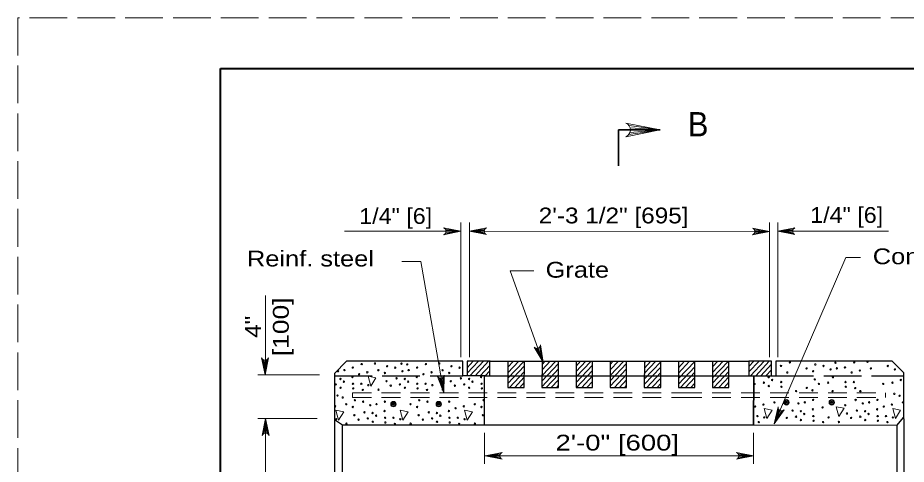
# Model space of a CAD drawing. Extents: x 1083.1 to 1117.1, y 697.4 to 719.4.
# Drawn here: x 1083.13 to 1091.89, y 714.95 to 719.35 of the extents above; entities that cross this region are included whole.
import ezdxf
from ezdxf.enums import TextEntityAlignment as Align

# ---------------------------------------------------------------- set-up
doc = ezdxf.new("R2010")
doc.units = 0
doc.header["$LTSCALE"] = 0.062
doc.linetypes.add('LONG_DASHED', pattern=[7.5, 6, -1.5])
doc.linetypes.add('MEDIUM_DASHED', pattern=[4.5, 3, -1.5])
doc.layers.add('1', color=7, linetype='Continuous', lineweight=13)

msp = doc.modelspace()

# ---------------------------------------------------------------- linework, layer by layer
at = {"layer": '1', "lineweight": 25}
for p, q in [((1085.12642, 718.85408), (1116.62642, 718.85408)), ((1090.6065, 715.96242), (1090.6065, 715.81983)), ((1087.783, 715.81983), (1087.783, 715.96233)), ((1087.78858, 715.96233), (1090.33942, 715.96233)), ((1090.56425, 715.96233), (1090.33942, 715.96233)), ((1090.34, 715.96233), (1090.34, 715.81983)), ((1090.56425, 715.81983), (1090.56425, 715.96233)), ((1090.56425, 715.81983), (1090.56425, 715.96233)), ((1087.73, 715.33367), (1087.73, 715.81983)), ((1087.73642, 715.81983), (1087.78242, 715.81983)), ((1087.78242, 715.81983), (1090.3455, 715.81983)), ((1086.24967, 715.39908), (1086.24967, 714.6575)), ((1086.25133, 715.38933), (1086.32992, 715.33367)), ((1091.80083, 715.33333), (1091.8655, 715.40867)), ((1091.86725, 715.39333), (1091.86725, 714.669)), ((1086.32992, 714.65083), (1086.32992, 715.33367)), ((1086.32992, 715.33367), (1087.73642, 715.33367)), ((1087.73642, 715.33367), (1090.38633, 715.33367)), ((1090.38633, 715.33367), (1091.80083, 715.33333)), ((1091.80083, 714.66842), (1091.80083, 715.33333))]:
    msp.add_line(p, q, dxfattribs=at)
at = {"layer": '1', "lineweight": 35}
for q in [(1089.46333, 718.24725), (1089.05217, 717.89125)]:
    msp.add_line((1089.05217, 718.24725), q, dxfattribs=at)
at = {"layer": '1'}
for p, q in [((1089.15517, 718.20008), (1089.46333, 718.24725)), ((1089.15875, 718.28983), (1089.46333, 718.24725)), ((1089.16683, 718.21983), (1089.46333, 718.24725)), ((1089.16908, 718.26875), (1089.46333, 718.24725)), ((1089.17225, 718.24725), (1089.46333, 718.24725)), ((1087.49642, 716.00258), (1087.49642, 717.33425)), ((1087.58358, 716.00375), (1087.58358, 717.33425)), ((1090.544, 716.00267), (1090.544, 717.33425)), ((1090.62583, 716.0035), (1090.62583, 717.33425)), ((1086.35, 717.24558), (1087.49642, 717.24558)), ((1087.34233, 717.22208), (1087.49642, 717.24558)), ((1087.34417, 717.26692), (1087.49642, 717.24558)), ((1087.34817, 717.23192), (1087.49642, 717.24558)), ((1087.34933, 717.25633), (1087.49642, 717.24558)), ((1087.35092, 717.24558), (1087.49642, 717.24558)), ((1087.73583, 717.26808), (1087.58358, 717.24675)), ((1087.73075, 717.2575), (1087.58358, 717.24675)), ((1087.72917, 717.24675), (1087.58358, 717.24675)), ((1087.73183, 717.23308), (1087.58358, 717.24675)), ((1087.73767, 717.22325), (1087.58358, 717.24675)), ((1087.58358, 717.24675), (1090.54392, 717.24458)), ((1090.38983, 717.221), (1090.54392, 717.24458)), ((1090.39167, 717.26583), (1090.54392, 717.24458)), ((1090.39567, 717.23083), (1090.54392, 717.24458)), ((1090.39683, 717.25533), (1090.54392, 717.24458)), ((1090.39842, 717.24458), (1090.54392, 717.24458)), ((1090.77817, 717.26783), (1090.62583, 717.2465)), ((1090.773, 717.25725), (1090.62583, 717.2465)), ((1090.77142, 717.2465), (1090.62583, 717.2465)), ((1090.77417, 717.23283), (1090.62583, 717.2465)), ((1090.78, 717.22292), (1090.62583, 717.2465)), ((1091.71783, 717.2465), (1090.62583, 717.2465)), ((1086.91533, 716.94842), (1087.10275, 716.94842)), ((1087.32858, 715.65258), (1087.10275, 716.94842)), ((1088.30708, 715.95333), (1087.98292, 716.85592)), ((1088.219, 716.85592), (1087.98292, 716.85592)), ((1085.57192, 715.8295), (1085.57192, 716.613)), ((1088.23817, 716.0915), (1088.30842, 715.95467)), ((1088.24983, 716.09008), (1088.30842, 715.95467)), ((1088.2605, 716.09217), (1088.30842, 715.95467)), ((1088.27258, 716.09917), (1088.30842, 715.95467)), ((1088.27992, 716.10792), (1088.30842, 715.95467)), ((1085.54433, 715.98183), (1085.56567, 715.8295)), ((1085.55483, 715.97667), (1085.56567, 715.8295)), ((1085.58917, 715.98358), (1085.56567, 715.8295)), ((1085.57933, 715.97775), (1085.56567, 715.8295)), ((1085.56567, 715.97508), (1085.56567, 715.8295)), ((1087.55875, 715.84417), (1087.67042, 715.96233)), ((1087.55875, 715.89792), (1087.61967, 715.96233)), ((1087.55875, 715.95158), (1087.56892, 715.96233)), ((1087.58658, 715.81992), (1087.72117, 715.96233)), ((1087.63742, 715.81992), (1087.77192, 715.96233)), ((1087.68817, 715.81992), (1087.783, 715.92042)), ((1087.96208, 715.74167), (1088.124, 715.91317)), ((1087.96217, 715.7955), (1088.11942, 715.96192)), ((1087.96233, 715.90317), (1088.01808, 715.96217)), ((1087.96233, 715.84933), (1088.06875, 715.96208)), ((1088.12417, 715.96192), (1087.96242, 715.96233)), ((1087.96242, 715.95692), (1087.9675, 715.96225)), ((1088.29842, 715.71517), (1088.4605, 715.88667)), ((1088.2985, 715.76908), (1088.4605, 715.9405)), ((1088.29867, 715.82292), (1088.43008, 715.962)), ((1088.29875, 715.93042), (1088.32883, 715.96225)), ((1088.29875, 715.87667), (1088.37942, 715.96208)), ((1088.46058, 715.96192), (1088.29892, 715.96233)), ((1088.635, 715.80758), (1088.78083, 715.96192)), ((1088.635, 715.75375), (1088.79692, 715.92525)), ((1088.63517, 715.86142), (1088.73025, 715.96208)), ((1088.63525, 715.91525), (1088.67958, 715.96225)), ((1088.79708, 715.96192), (1088.63533, 715.96233)), ((1088.97133, 715.71575), (1089.13333, 715.88725)), ((1088.97142, 715.76958), (1089.13342, 715.94108)), ((1088.97158, 715.82342), (1089.1025, 715.962)), ((1088.97167, 715.931), (1089.00117, 715.96225)), ((1088.97167, 715.87725), (1089.05175, 715.96208)), ((1089.1335, 715.96192), (1088.97175, 715.96233)), ((1089.30775, 715.733), (1089.46975, 715.9045)), ((1089.30783, 715.78683), (1089.46983, 715.95833)), ((1089.308, 715.84067), (1089.42267, 715.96208)), ((1089.30808, 715.8945), (1089.372, 715.96217)), ((1089.30817, 715.94833), (1089.32142, 715.96225)), ((1089.46992, 715.96192), (1089.30825, 715.96233)), ((1089.64425, 715.73758), (1089.80625, 715.909)), ((1089.64433, 715.79142), (1089.8055, 715.96192)), ((1089.64442, 715.84508), (1089.75483, 715.96208)), ((1089.6445, 715.899), (1089.70425, 715.96217)), ((1089.64458, 715.95275), (1089.65358, 715.96225)), ((1089.80642, 715.96192), (1089.64467, 715.96233)), ((1089.98075, 715.74517), (1090.14267, 715.91658)), ((1089.98083, 715.799), (1090.13475, 715.96192)), ((1089.981, 715.96033), (1089.98283, 715.96225)), ((1089.981, 715.90667), (1090.03342, 715.96217)), ((1089.981, 715.85283), (1090.08417, 715.96208)), ((1090.14283, 715.96192), (1089.98108, 715.96233)), ((1090.34, 715.85683), (1090.43975, 715.96233)), ((1090.34, 715.9105), (1090.38892, 715.96225)), ((1090.35592, 715.81983), (1090.4905, 715.96233)), ((1090.40658, 715.81983), (1090.54125, 715.96233)), ((1090.45733, 715.81983), (1090.56425, 715.93308)), ((1090.50808, 715.81983), (1090.56425, 715.87933)), ((1086.10392, 715.8295), (1085.49325, 715.8295)), ((1087.28275, 715.79933), (1087.32858, 715.65258)), ((1087.294, 715.796), (1087.32858, 715.65258)), ((1087.30483, 715.79617), (1087.32858, 715.65258)), ((1087.31792, 715.80108), (1087.32858, 715.65258)), ((1087.32667, 715.80842), (1087.32858, 715.65258)), ((1087.53633, 715.81983), (1087.73642, 715.81983)), ((1087.73883, 715.81983), (1087.783, 715.86667)), ((1087.97842, 715.70525), (1088.12392, 715.85925)), ((1088.02908, 715.70517), (1088.12383, 715.8055)), ((1088.33975, 715.70525), (1088.46033, 715.83283)), ((1088.63992, 715.70525), (1088.79683, 715.87142)), ((1088.69058, 715.70517), (1088.79667, 715.81758)), ((1089.01217, 715.70525), (1089.13317, 715.83342)), ((1089.33233, 715.70525), (1089.46975, 715.85067)), ((1089.383, 715.70508), (1089.46958, 715.79683)), ((1089.66458, 715.70525), (1089.80617, 715.85517)), ((1089.71517, 715.70508), (1089.806, 715.80133)), ((1089.99383, 715.70525), (1090.14258, 715.86275)), ((1090.04442, 715.70517), (1090.14242, 715.80892)), ((1090.38692, 715.81983), (1090.38692, 715.3415)), ((1088.07967, 715.705), (1088.12375, 715.75167)), ((1088.39042, 715.70508), (1088.46025, 715.779)), ((1088.441, 715.70492), (1088.46017, 715.72517)), ((1088.74117, 715.705), (1088.79667, 715.76375)), ((1088.79183, 715.70492), (1088.79658, 715.71)), ((1089.06275, 715.70508), (1089.13317, 715.77958)), ((1089.11342, 715.70492), (1089.13308, 715.72575)), ((1089.43358, 715.705), (1089.46958, 715.74308)), ((1089.76575, 715.705), (1089.806, 715.7475)), ((1090.09508, 715.705), (1090.14233, 715.75508)), ((1086.26542, 715.47833), (1086.29108, 715.38092)), ((1090.63208, 715.49233), (1090.59, 715.34442)), ((1090.63967, 715.48333), (1090.59, 715.34442)), ((1090.64883, 715.47758), (1090.59, 715.34442)), ((1090.67383, 715.47583), (1090.59, 715.34442)), ((1090.66242, 715.4745), (1090.59, 715.34442)), ((1090.63117, 715.4375), (1090.59, 715.34442)), ((1086.0795, 715.39908), (1085.49325, 715.39908)), ((1085.54833, 715.245), (1085.57192, 715.39908)), ((1085.55825, 715.25083), (1085.57192, 715.39908)), ((1085.57192, 711.969), (1085.57192, 715.39908)), ((1085.57192, 715.2535), (1085.57192, 715.39908)), ((1085.58267, 715.25192), (1085.57192, 715.39908)), ((1085.59325, 715.24675), (1085.57192, 715.39908)), ((1087.73, 715.25717), (1087.73, 714.9505)), ((1090.38633, 715.25717), (1090.38633, 714.9505)), ((1087.88875, 715.05017), (1087.73642, 715.02883)), ((1087.88358, 715.03958), (1087.73642, 715.02883)), ((1087.8335, 715.02883), (1087.73642, 715.02883)), ((1087.882, 715.02883), (1087.73642, 715.02883)), ((1087.88467, 715.01517), (1087.73642, 715.02883)), ((1087.8905, 715.00525), (1087.73642, 715.02883)), ((1087.73642, 715.02883), (1089.35158, 715.02883)), ((1089.35158, 715.02883), (1090.38633, 715.02883)), ((1090.23225, 715.00525), (1090.38633, 715.02883)), ((1090.234, 715.05017), (1090.38633, 715.02883)), ((1090.23808, 715.01517), (1090.38633, 715.02883)), ((1090.23917, 715.03958), (1090.38633, 715.02883)), ((1090.24075, 715.02883), (1090.38633, 715.02883)), ((1090.28925, 715.02883), (1090.38633, 715.02883))]:
    msp.add_line(p, q, dxfattribs=at)
at = {"layer": '1', "linetype": 'LONG_DASHED', "lineweight": 25}
msp.add_line((1086.24967, 715.81983), (1087.5165, 715.81983), dxfattribs=at)
at = {"layer": '1', "linetype": 'LONG_DASHED'}
for p, q in [((1086.42908, 715.65267), (1086.42908, 715.60392)), ((1091.68783, 715.65267), (1091.68783, 715.60392))]:
    msp.add_line(p, q, dxfattribs=at)
at = {"layer": '1', "linetype": 'MEDIUM_DASHED'}
for p, q in [((1086.42908, 715.65267), (1089.69008, 715.65267)), ((1089.69008, 715.65267), (1091.68783, 715.65267)), ((1086.42908, 715.60392), (1089.69008, 715.60392)), ((1089.69008, 715.60392), (1091.68783, 715.60392))]:
    msp.add_line(p, q, dxfattribs=at)
at = {"layer": '1', "linetype": 'LONG_DASHED'}
msp.add_lwpolyline([(1083.12642, 697.35408), (1117.12642, 697.35408), (1117.12642, 719.35408), (1083.12642, 719.35408)], close=True, dxfattribs=at)
at = {"layer": '1', "lineweight": 25}
for points in [[(1116.62642, 697.85408), (1085.12642, 697.85408), (1085.12642, 718.85408)], [(1091.86725, 715.39358), (1091.86725, 715.84767), (1091.75275, 715.96408), (1090.6065, 715.96242)], [(1087.73642, 715.81983), (1087.5165, 715.81983), (1087.5165, 715.96233), (1086.37, 715.96233), (1086.24967, 715.84292), (1086.24967, 715.39908)], [(1087.78858, 715.96233), (1087.55875, 715.96233), (1087.55875, 715.81983)], [(1087.96242, 715.96233), (1087.96192, 715.70525), (1088.12367, 715.70483), (1088.12417, 715.96192)], [(1088.29892, 715.96233), (1088.29833, 715.70525), (1088.46008, 715.70483), (1088.46058, 715.96192)], [(1088.63533, 715.96233), (1088.63483, 715.70525), (1088.7965, 715.70483), (1088.79708, 715.96192)], [(1088.97175, 715.96233), (1088.97125, 715.70525), (1089.133, 715.70483), (1089.1335, 715.96192)], [(1089.30825, 715.96233), (1089.30767, 715.70525), (1089.46942, 715.70483), (1089.46992, 715.96192)], [(1089.64467, 715.96233), (1089.64417, 715.70525), (1089.80583, 715.70483), (1089.80642, 715.96192)], [(1089.98108, 715.96233), (1089.98058, 715.70525), (1090.14233, 715.70483), (1090.14283, 715.96192)], [(1090.3455, 715.81983), (1090.38633, 715.81983), (1090.6065, 715.81983)], [(1090.38633, 715.33367), (1090.38692, 715.81983), (1090.38633, 715.33367)]]:
    msp.add_lwpolyline(points, dxfattribs=at)
at = {"layer": '1', "lineweight": 40}
msp.add_lwpolyline([(1085.12642, 718.85408), (1116.62642, 718.85408), (1116.62642, 697.85408), (1085.12642, 697.85408)], close=True, dxfattribs=at)
msp.add_lwpolyline([(1085.12642, 718.85408), (1116.62642, 718.85408), (1116.62642, 697.85408), (1085.12642, 697.85408)], close=True, dxfattribs=at)
at = {"layer": '1'}
for points in [[(1089.12692, 718.17992), (1089.46333, 718.24725), (1089.12692, 718.3145)], [(1087.32825, 717.212), (1087.49642, 717.24558), (1087.32825, 717.27925)], [(1087.75183, 717.21308), (1087.58358, 717.24675), (1087.75183, 717.28042)], [(1090.37575, 717.21092), (1090.54392, 717.24458), (1090.37575, 717.27817)], [(1090.79408, 717.21283), (1090.62583, 717.2465), (1090.79408, 717.28017)], [(1090.59, 715.34442), (1091.29525, 716.986), (1091.44108, 716.986)], [(1088.28483, 716.12458), (1088.30842, 715.95467), (1088.22125, 716.1025)], [(1085.59925, 715.99775), (1085.56567, 715.8295), (1085.532, 715.99775)], [(1087.33433, 715.824), (1087.32858, 715.65258), (1087.268, 715.813)], [(1086.29108, 715.38092), (1086.34333, 715.46308), (1086.26542, 715.47833)], [(1090.68875, 715.48467), (1090.59, 715.34442), (1090.62725, 715.51183)], [(1085.53825, 715.23083), (1085.57192, 715.39908), (1085.60558, 715.23083)], [(1087.90467, 714.99517), (1087.73642, 715.02883), (1087.90467, 715.0625)], [(1090.21808, 714.99517), (1090.38633, 715.02883), (1090.21808, 715.0625)]]:
    msp.add_lwpolyline(points, dxfattribs=at)
for points in [[(1086.58267, 715.81408), (1086.60833, 715.71683), (1086.6605, 715.799)], [(1086.89983, 715.47833), (1086.9255, 715.38092), (1086.97775, 715.46308)], [(1087.53425, 715.47833), (1087.55992, 715.38092), (1087.61208, 715.46308)], [(1090.49008, 715.4955), (1090.51575, 715.39817), (1090.568, 715.48033)], [(1091.20017, 715.51442), (1091.22583, 715.41708), (1091.278, 715.49925)], [(1091.75892, 715.4955), (1091.78458, 715.39817), (1091.83675, 715.48033)]]:
    msp.add_lwpolyline(points, close=True, dxfattribs=at)
at = {"layer": '1', "linetype": 'LONG_DASHED', "lineweight": 25}
msp.add_lwpolyline([(1090.6065, 715.81983), (1091.67575, 715.81983), (1091.86725, 715.81983)], dxfattribs=at)
at = {"layer": '1'}
for centre, radius in [((1086.8323, 715.53968), 0.02655), ((1086.8323, 715.53968), 0.01987), ((1086.8323, 715.53968), 0.01149), ((1086.8323, 715.53968), 0.00431), ((1087.27929, 715.53968), 0.02655), ((1087.27929, 715.53968), 0.02655), ((1087.27929, 715.53968), 0.01987), ((1087.27929, 715.53968), 0.01149), ((1087.27929, 715.53968), 0.00431), ((1090.70991, 715.55725), 0.02655), ((1090.70991, 715.55725), 0.01987), ((1090.70991, 715.55725), 0.01149), ((1090.70991, 715.55725), 0.00431), ((1091.15691, 715.55725), 0.02655), ((1091.15691, 715.55725), 0.02655), ((1091.15691, 715.55725), 0.01987), ((1091.15691, 715.55725), 0.01149), ((1091.15691, 715.55725), 0.00431)]:
    msp.add_circle(centre, radius, dxfattribs=at)
for centre, radius, start, end in [((1089.09975, 718.2473), 0.07261, 292.08605, 67.91218), ((1087.31464, 717.24565), 0.03631, 292.08605, 67.91218), ((1087.76538, 717.24681), 0.03631, 112.08782, 247.91395), ((1090.36215, 717.24459), 0.03631, 292.08605, 67.91218), ((1090.80768, 717.24653), 0.03631, 112.08782, 247.91395), ((1088.24856, 716.12636), 0.03631, 221.29191, 357.11803), ((1085.5656, 716.01131), 0.03631, 202.08782, 337.91395), ((1087.29891, 715.83191), 0.03631, 211.46424, 347.29037), ((1090.66345, 715.51071), 0.03631, 178.25218, 314.07831), ((1085.57195, 715.21728), 0.03631, 22.08782, 157.91395), ((1087.91824, 715.02886), 0.03631, 112.08782, 247.91395), ((1090.20453, 715.02886), 0.03631, 292.08605, 67.91218)]:
    msp.add_arc(centre, radius, start, end, dxfattribs=at)
for centre in [(1091.50946, 715.9579), (1086.34855, 715.87575), (1086.43166, 715.90015), (1086.51931, 715.93441), (1086.65037, 715.94073), (1086.68373, 715.87452), (1086.77027, 715.91353), (1086.85105, 715.89931), (1086.91105, 715.93922), (1086.96841, 715.93099), (1086.98295, 715.87575), (1087.06606, 715.90015), (1087.15371, 715.93441), (1087.28477, 715.94073), (1087.31813, 715.87452), (1087.40467, 715.91353), (1087.48545, 715.89931), (1090.65634, 715.91732), (1090.744, 715.95157), (1090.90841, 715.89169), (1090.99496, 715.9307), (1091.07574, 715.91648), (1091.14594, 715.882), (1091.1931, 715.94816), (1091.20764, 715.89292), (1091.28763, 715.90134), (1091.3784, 715.95157), (1091.43407, 715.87081), (1091.54282, 715.89169), (1091.71014, 715.91648), (1091.78035, 715.882), (1086.28685, 715.86483), (1086.31006, 715.78776), (1086.42854, 715.80741), (1086.49356, 715.83461), (1086.57498, 715.85364), (1086.74886, 715.84732), (1086.86363, 715.79476), (1086.92126, 715.86483), (1086.94446, 715.78776), (1087.06294, 715.80741), (1087.12797, 715.83461), (1087.20938, 715.85364), (1087.38326, 715.84732), (1087.49803, 715.79476), (1087.57887, 715.78776), (1087.69734, 715.80741), (1090.53475, 715.80493), (1090.71825, 715.85178), (1090.97354, 715.86448), (1090.98898, 715.78288), (1091.16915, 715.80493), (1091.35265, 715.85178), (1086.26264, 715.73397), (1086.31091, 715.70101), (1086.34374, 715.76118), (1086.43367, 715.7403), (1086.4362, 715.69407), (1086.51593, 715.7403), (1086.58354, 715.7267), (1086.76429, 715.76571), (1086.80542, 715.72216), (1086.89704, 715.73397), (1086.94531, 715.70101), (1086.97814, 715.76118), (1087.06807, 715.7403), (1087.0706, 715.69407), (1087.15033, 715.7403), (1087.21794, 715.7267), (1087.3987, 715.76571), (1087.43983, 715.72216), (1087.53144, 715.73397), (1087.57971, 715.70101), (1087.61254, 715.76118), (1087.70247, 715.7403), (1087.70501, 715.69407), (1090.39571, 715.73933), (1090.48733, 715.75114), (1090.5356, 715.71818), (1090.56843, 715.77834), (1090.65835, 715.75747), (1090.66089, 715.71124), (1090.91016, 715.69943), (1091.03011, 715.73933), (1091.12173, 715.75114), (1091.29275, 715.75747), (1091.29529, 715.71124), (1091.37502, 715.75747), (1091.38871, 715.69763), (1091.66451, 715.73933), (1091.75613, 715.75114), (1091.83723, 715.77834), (1086.28093, 715.62394), (1086.33317, 715.60491), (1086.52962, 715.68047), (1086.68547, 715.68226), (1087.16402, 715.68047), (1087.31987, 715.68226), (1090.80479, 715.66769), (1090.96667, 715.67586), (1091.16494, 715.66769), (1091.4392, 715.66769), (1091.77442, 715.6411), (1091.82666, 715.62207), (1086.25778, 715.51782), (1086.36652, 715.53869), (1086.45307, 715.5777), (1086.53385, 715.56349), (1086.60405, 715.52901), (1086.66575, 715.53992), (1086.74886, 715.56433), (1087.00093, 715.53869), (1087.08747, 715.5777), (1087.16825, 715.56349), (1087.38326, 715.56433), (1087.52658, 715.51782), (1087.63533, 715.53869), (1087.72187, 715.5777), (1090.48246, 715.53498), (1090.59121, 715.55586), (1090.82874, 715.54618), (1090.89044, 715.55709), (1090.97354, 715.5815), (1091.29075, 715.52866), (1091.39294, 715.58066), (1091.46314, 715.54618), (1091.52484, 715.55709), (1091.60795, 715.5815), (1091.75127, 715.53498), (1091.86002, 715.55586), (1086.43166, 715.51149), (1086.44709, 715.42989), (1086.54643, 715.45893), (1086.62726, 715.45194), (1086.74574, 715.47158), (1087.06606, 715.51149), (1087.0815, 715.42989), (1087.18083, 715.45893), (1087.26167, 715.45194), (1087.38014, 715.47158), (1087.44517, 715.49879), (1087.70046, 715.51149), (1087.7159, 715.42989), (1090.40105, 715.51595), (1090.77112, 715.4761), (1090.85195, 715.46911), (1090.88563, 715.44252), (1090.97043, 715.48875), (1091.06624, 715.5068), (1091.30618, 715.44705), (1091.40552, 715.4761), (1091.48635, 715.46911), (1091.52003, 715.44252), (1091.60483, 715.48875), (1091.66985, 715.51595), (1086.26634, 715.39087), (1086.36827, 715.34643), (1086.48822, 715.38634), (1086.57984, 715.39815), (1086.62811, 715.36518), (1086.66094, 715.42535), (1086.75087, 715.40447), (1086.7534, 715.35824), (1086.83313, 715.40447), (1086.84682, 715.34464), (1086.90074, 715.39087), (1087.00267, 715.34643), (1087.12263, 715.38634), (1087.21424, 715.39815), (1087.26251, 715.36518), (1087.29534, 715.42535), (1087.38527, 715.40447), (1087.38781, 715.35824), (1087.46753, 715.40447), (1087.48122, 715.34464), (1087.53515, 715.39087), (1087.63707, 715.34643), (1090.42341, 715.42164), (1090.43711, 715.36181), (1090.49103, 715.40804), (1090.71291, 715.40351), (1090.80453, 715.41532), (1090.8528, 715.38235), (1090.97555, 715.42164), (1090.97809, 715.37541), (1091.07151, 715.36181), (1091.12543, 715.40804), (1091.22736, 715.3636), (1091.34731, 715.40351), (1091.43893, 715.41532), (1091.4872, 715.38235), (1091.60996, 715.42164), (1091.61249, 715.37541), (1091.69222, 715.42164), (1091.70591, 715.36181), (1091.75983, 715.40804)]:
    msp.add_ellipse(centre, major_axis=(0, 0.00718), ratio=0.944544, dxfattribs=at)

# ---------------------------------------------------------------- texts
for s, height, width, p in [('B', 0.24, 0.95, (1089.737, 718.18317)), ('2\'-3 1/2" [695]', 0.156, 1.15, (1088.26592, 717.32392)), ('Reinf. steel', 0.156, 1.2, (1085.38783, 716.8985)), ('Construction joint', 0.156, 1.2, (1091.56175, 716.92083)), ('2\'-0" [600]', 0.156, 1.3, (1088.43175, 715.08142))]:
    msp.add_text(s, height=height, dxfattribs=dict(at, width=width)).set_placement(p)
for s, width, p in [('1/4" [6]', 1.1, (1086.85496, 717.31867)), ('1/4" [6]', 1.1, (1091.30446, 717.32908)), ('Grate', 1.2, (1088.64738, 716.78808))]:
    msp.add_text(s, height=0.156, dxfattribs=dict(at, width=width)).set_placement(p, align=Align.CENTER)
for s, width, p in [('[100]', 1.25, (1085.79983, 716.30283)), ('4"', 1.15, (1085.52575, 716.30283))]:
    msp.add_text(s, height=0.156, rotation=90, dxfattribs=dict(at, width=width)).set_placement(p, align=Align.CENTER)

doc.saveas('drawing.dxf')
